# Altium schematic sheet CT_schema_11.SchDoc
size 389 x 278 mm
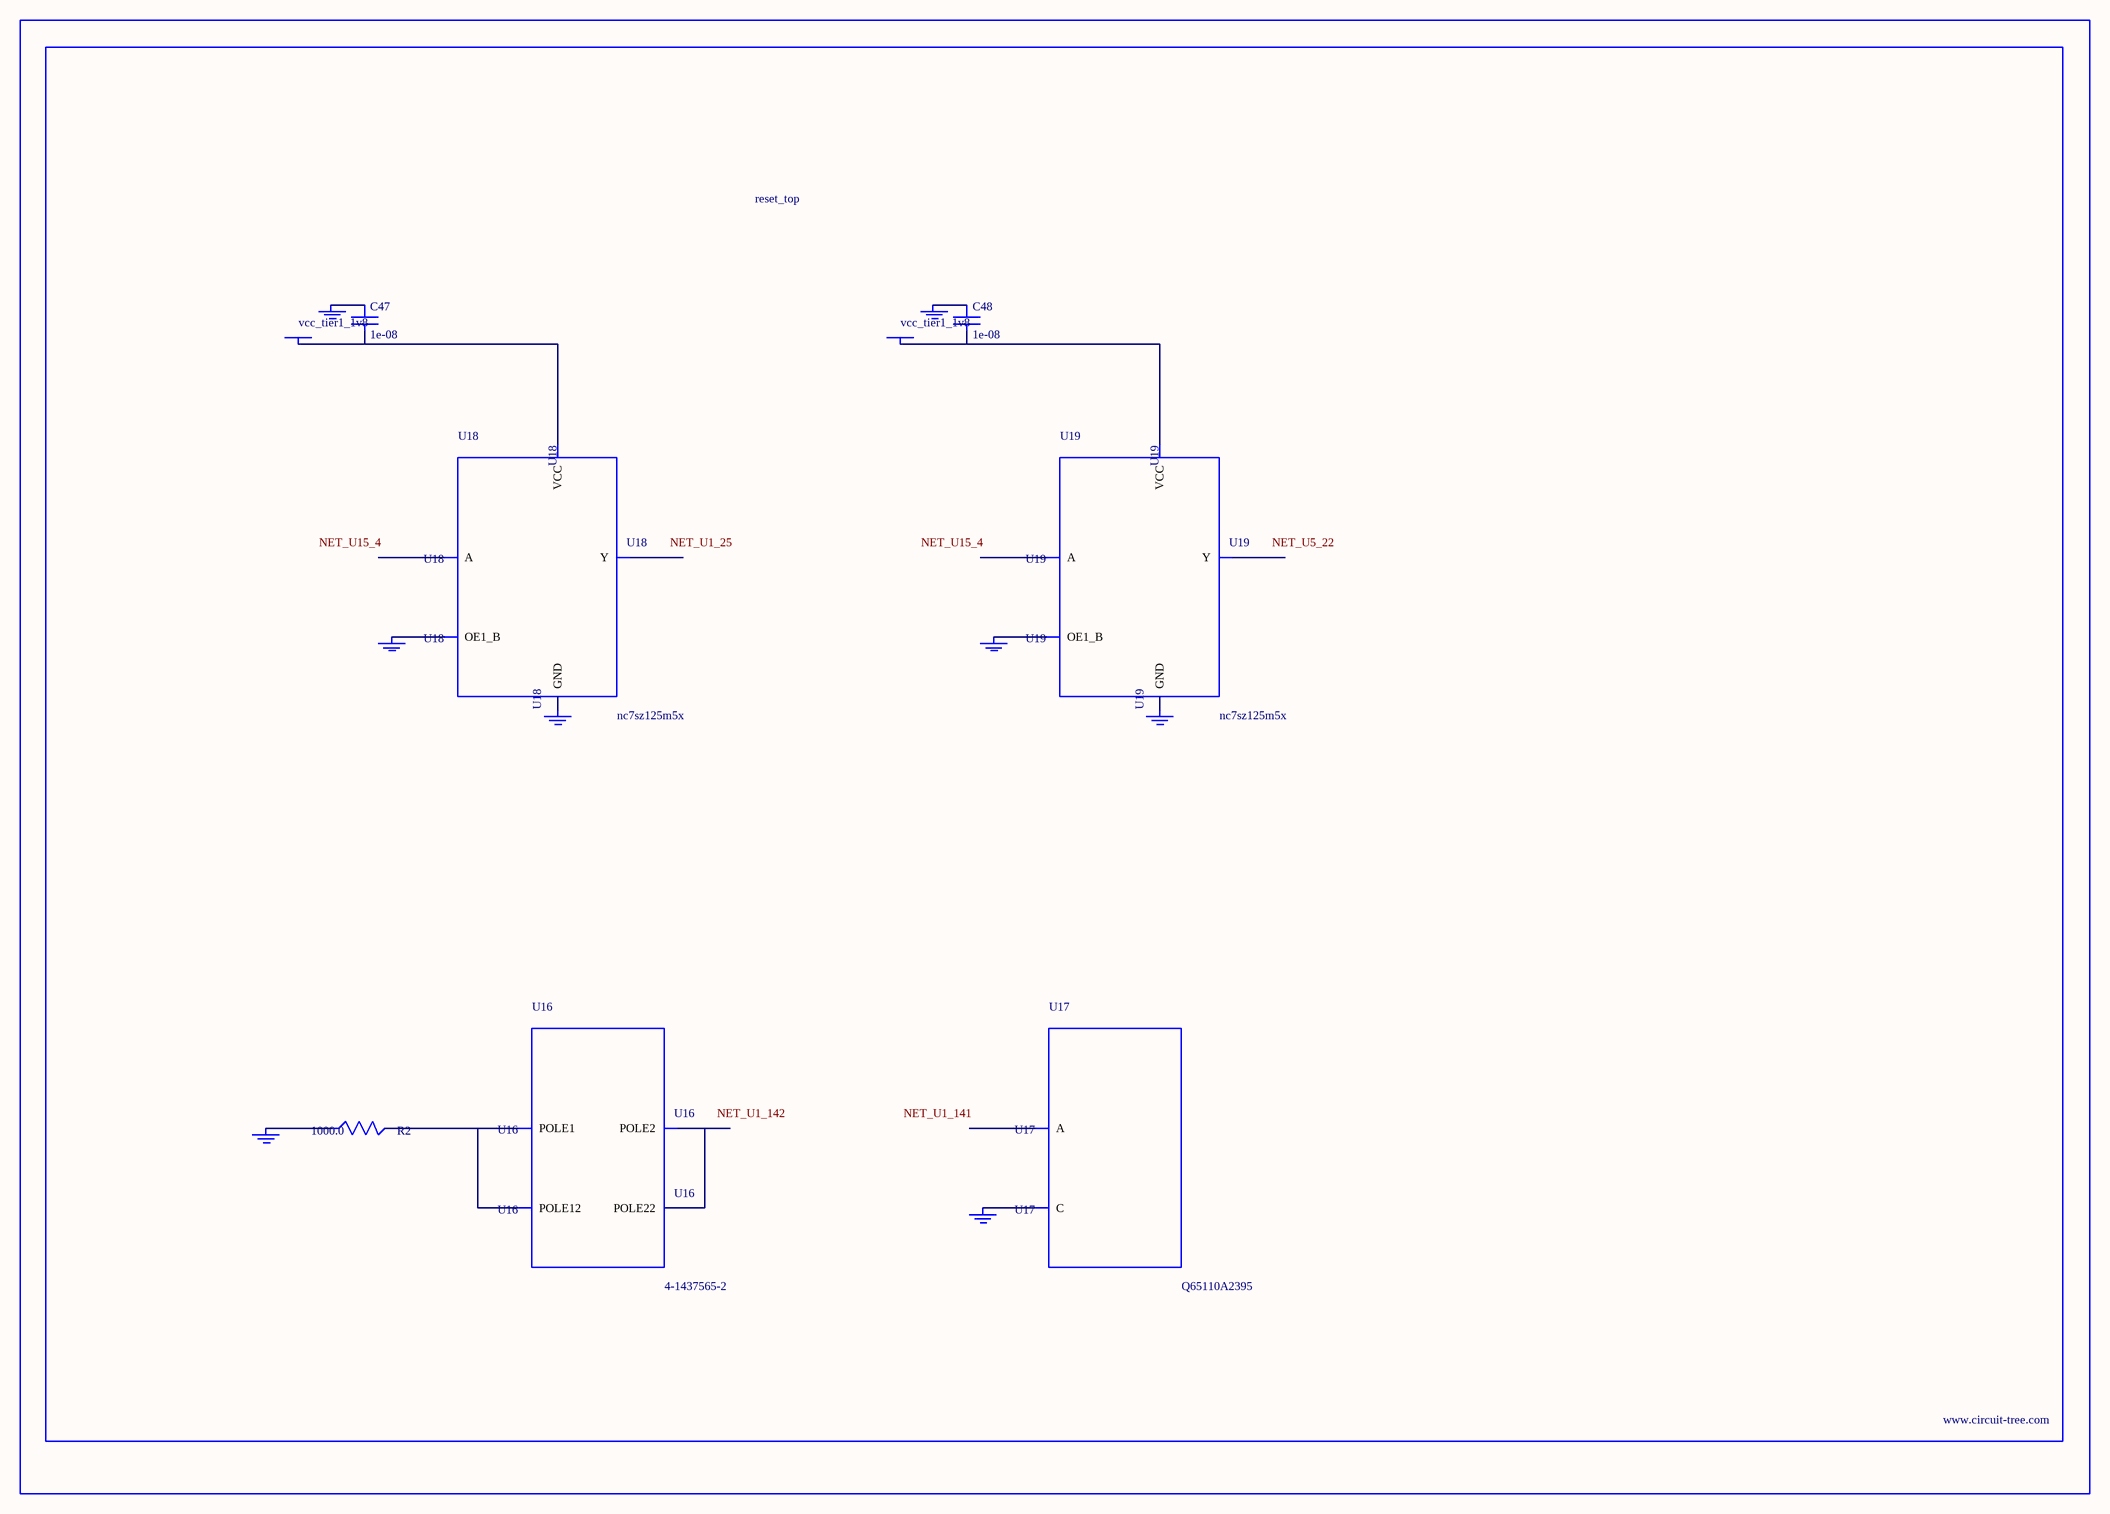
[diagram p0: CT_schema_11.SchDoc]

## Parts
BORDER10  (no value)
C47  1e-08  [C0402]
C48  1e-08  [C0402]
GND_INSTANCE_10_0  (no value)
GND_INSTANCE_10_1  (no value)
GND_INSTANCE_10_2  (no value)
GND_INSTANCE_10_3  (no value)
GND_INSTANCE_10_4  (no value)
GND_INSTANCE_10_5  (no value)
GND_INSTANCE_10_6  (no value)
GND_INSTANCE_10_7  (no value)
POWER_INSTANCE_10_0  vcc_tier1_1v8
POWER_INSTANCE_10_1  vcc_tier1_1v8
R2  1000.0  [R0603]
U16  4-1437565-2  [SW_4-1437565-2]
U17  Q65110A2395  [LGM67K-G1J2-24-Z]
U18  nc7sz125m5x  [NC7SZ125M5X]
U19  nc7sz125m5x  [NC7SZ125M5X]

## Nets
NetC47_1: C47.1 GND_INSTANCE_10_2.0(GND)
NetC47_2: C47.2 POWER_INSTANCE_10_0.0(PWR) U18.5(VCC)
NetC48_1: C48.1 GND_INSTANCE_10_5.0(GND)
NetC48_2: C48.2 POWER_INSTANCE_10_1.0(PWR) U19.5(VCC)
NetGND_INSTANCE_10_0_0: GND_INSTANCE_10_0.0(GND) R2.1
NetGND_INSTANCE_10_1_0: GND_INSTANCE_10_1.0(GND) U17.C
NetGND_INSTANCE_10_3_0: GND_INSTANCE_10_3.0(GND) U18.1(OE1_B)
NetGND_INSTANCE_10_4_0: GND_INSTANCE_10_4.0(GND) U18.3(GND)
NetGND_INSTANCE_10_6_0: GND_INSTANCE_10_6.0(GND) U19.1(OE1_B)
NetGND_INSTANCE_10_7_0: GND_INSTANCE_10_7.0(GND) U19.3(GND)
NetR2_2: R2.2 U16.1(POLE1) U16.2(POLE12)
NetU16_3: U16.3(POLE2) U16.4(POLE22)

Not connected (* = marked no-connect by the designer): U17 A; U18 2(A) 4(Y); U19 2(A) 4(Y)

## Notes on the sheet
- Labels drawn without touching a wire or pin: NET_U1_25, NET_U1_141, NET_U1_142, NET_U5_22, NET_U15_4

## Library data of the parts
BORDER10 = BORDER_PAGE10
C47 C48 = C0402C103K3RAC
GND_INSTANCE_10_0-GND_INSTANCE_10_7 = GND
POWER_INSTANCE_10_0 POWER_INSTANCE_10_1 = PWR
R2 = RC0603JR-071KL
